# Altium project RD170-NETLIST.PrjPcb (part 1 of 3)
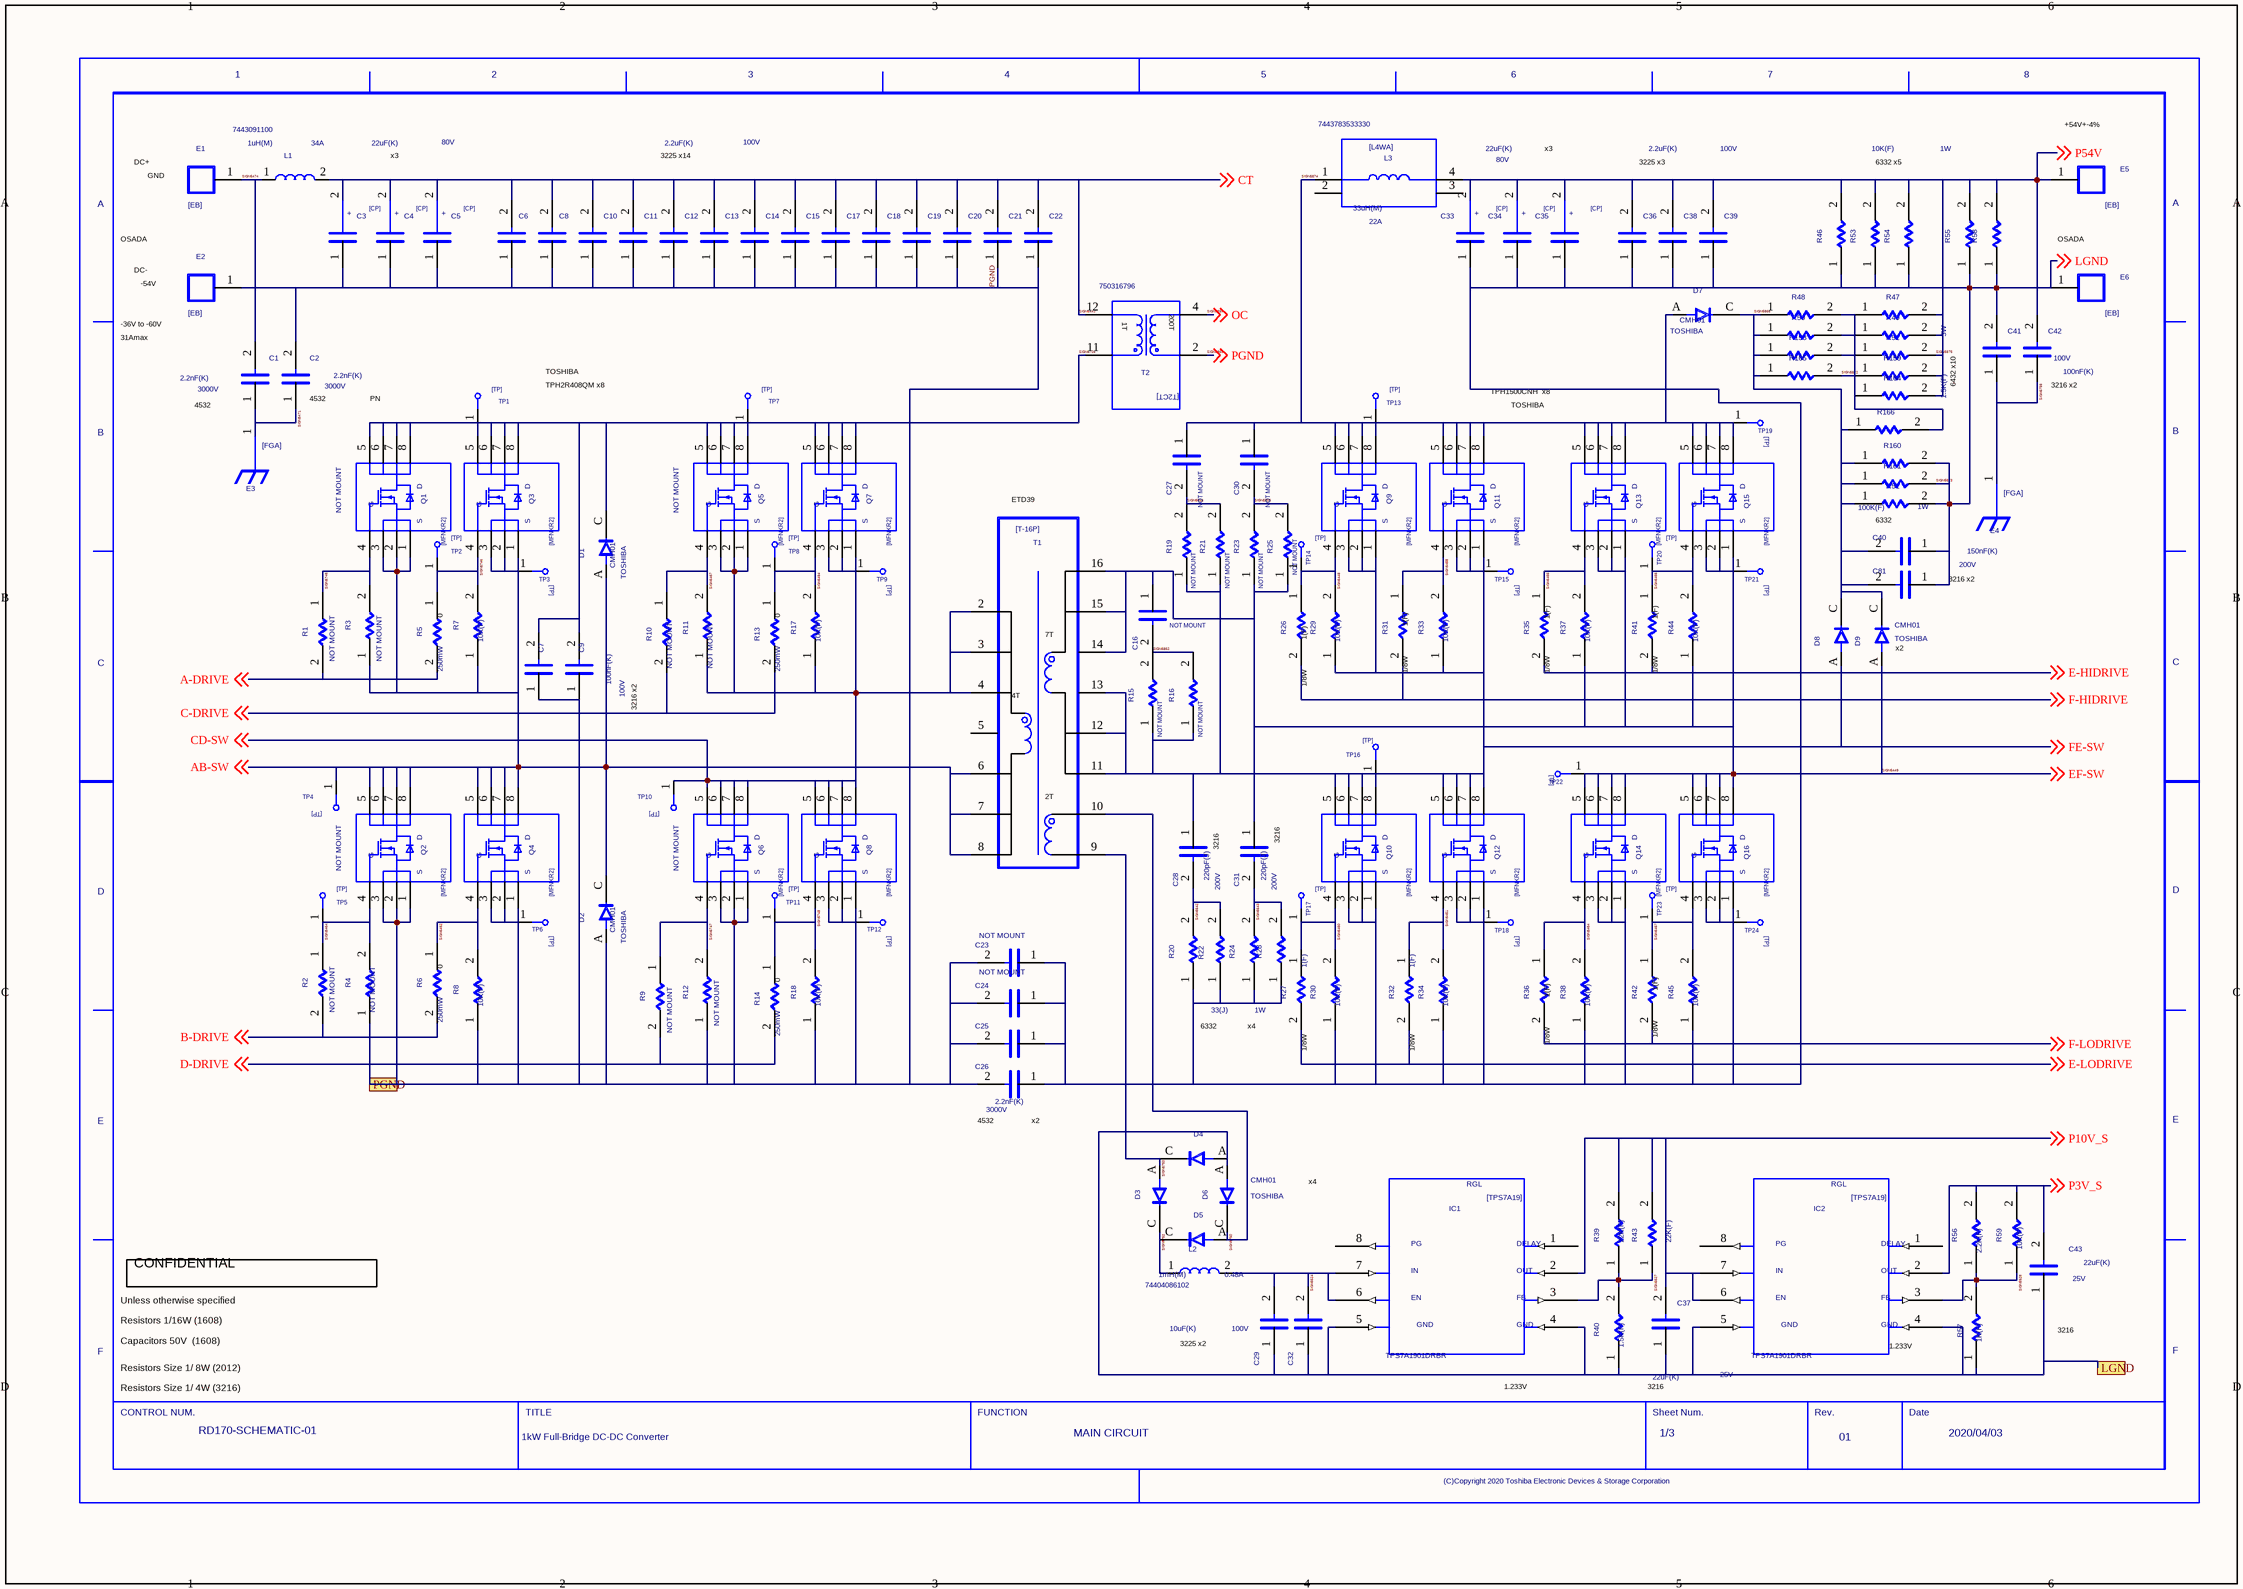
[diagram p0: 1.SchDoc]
3 sheets, 345 parts. Net scope: flat (ports and power ports of the same name join across sheets).
Sheets:
  1.SchDoc
  2.SchDoc
  3.SchDoc

## Sheet 1.SchDoc
size 420 x 297 mm

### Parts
(Parts that share a designator on the sheet are numbered #1, #2 ... from top to bottom, then left to right.)
C1  VAL2: 3000V  VAL1: 2.2nF(K)  (hidden comment: C)
C2  VAL2: 3000V  VAL1: 2.2nF(K)  (hidden comment: C)
C3  CP  (value not drawn)
C4  VAL2: 80V  VAL1: 22uF(K)  (hidden comment: CP)
C5  CP  (value not drawn)
C6  C  (value not drawn)
C7  C  (value not drawn)
C8  C  (value not drawn)
C9  VAL2: 100V  VAL1: 100nF(K)  (hidden comment: C)
C10  C  (value not drawn)
C11  C  (value not drawn)
C12  C  (value not drawn)
C13  VAL2: 100V  VAL1: 2.2uF(K)  (hidden comment: C)
C14  C  (value not drawn)
C15  C  (value not drawn)
C16  NOTMOUNT: NOT MOUNT  (hidden comment: C)
C17  C  (value not drawn)
C18  C  (value not drawn)
C19  C  (value not drawn)
C20  C  (value not drawn)
C21  C  (value not drawn)
C22  C  (value not drawn)
C23  NOTMOUNT: NOT MOUNT  (hidden comment: C)
C24  NOTMOUNT: NOT MOUNT  (hidden comment: C)
C25  C  (value not drawn)
C26  VAL2: 3000V  VAL1: 2.2nF(K)  (hidden comment: C)
C27  NOTMOUNT: NOT MOUNT  (hidden comment: C)
C28  VAL2: 200V  VAL1: 220pF(J)  (hidden comment: C)
C29  VAL2: 100V  VAL1: 10uF(K)  (hidden comment: C)
C30  NOTMOUNT: NOT MOUNT  (hidden comment: C)
C31  VAL2: 200V  VAL1: 220pF(J)  (hidden comment: C)
C32  C  (value not drawn)
C33  VAL2: 80V  VAL1: 22uF(K)  (hidden comment: CP)
C34  CP  (value not drawn)
C35  CP  (value not drawn)
C36  C  (value not drawn)
C37  VAL2: 25V  VAL1: 22uF(K)  (hidden comment: C)
C38  VAL2: 100V  VAL1: 2.2uF(K)  (hidden comment: C)
C39  C  (value not drawn)
C40  VAL2: 200V  VAL1: 150nF(K)  (hidden comment: C)
C41  C  (value not drawn)
C42  VAL2: 100V  VAL1: 100nF(K)  (hidden comment: C)
C43  VAL2: 25V  VAL1: 22uF(K)  (hidden comment: C)
C81  C  (value not drawn)
D1  USERCOMPTEXT3: TOSHIBA  VAL3: CMH01  (hidden comment: D)
D2  USERCOMPTEXT3: TOSHIBA  VAL3: CMH01  (hidden comment: D)
D3  D  (value not drawn)
D4  D  (value not drawn)
D5  D  (value not drawn)
D6  USERCOMPTEXT3: TOSHIBA  VAL3: CMH01  (hidden comment: D)
D7  USERCOMPTEXT3: TOSHIBA  VAL3: CMH01  (hidden comment: D)
D8  D  (value not drawn)
D9  USERCOMPTEXT3: TOSHIBA  VAL3: CMH01  (hidden comment: D)
E1  EB  (value not drawn)
E2  EB  (value not drawn)
E3  FGA  (value not drawn)
E4  FGA  (value not drawn)
E5  EB  (value not drawn)
E6  EB  (value not drawn)
IC1  VAL3: TPS7A1901DRBR  (hidden comment: TPS7A19)
IC2  VAL3: TPS7A1901DRBR  (hidden comment: TPS7A19)
L1  VAL3: 7443091100  VAL2: 34A  VAL1: 1uH(M)  (hidden comment: L)
L2  VAL3: 74404086102  VAL2: 0.48A  VAL1: 1mH(M)  (hidden comment: L)
L3  VAL3: 7443783533330  VAL2: 22A  VAL1: 33uH(M)  (hidden comment: L4WA)
Q1  NOTMOUNT: NOT MOUNT  (hidden comment: MFNKR2)
Q2  NOTMOUNT: NOT MOUNT  (hidden comment: MFNKR2)
Q3  MFNKR2  (value not drawn)
Q4  MFNKR2  (value not drawn)
Q5  NOTMOUNT: NOT MOUNT  (hidden comment: MFNKR2)
Q6  NOTMOUNT: NOT MOUNT  (hidden comment: MFNKR2)
Q7  MFNKR2  (value not drawn)
Q8  MFNKR2  (value not drawn)
Q9  MFNKR2  (value not drawn)
Q10  MFNKR2  (value not drawn)
Q11  MFNKR2  (value not drawn)
Q12  MFNKR2  (value not drawn)
Q13  MFNKR2  (value not drawn)
Q14  MFNKR2  (value not drawn)
Q15  MFNKR2  (value not drawn)
Q16  MFNKR2  (value not drawn)
R1  NOTMOUNT: NOT MOUNT  (hidden comment: R)
R2  NOTMOUNT: NOT MOUNT  (hidden comment: R)
R3  NOTMOUNT: NOT MOUNT  (hidden comment: R)
R4  NOTMOUNT: NOT MOUNT  (hidden comment: R)
R5  VAL2: 250mW  (hidden comment: R)
R6  VAL2: 250mW  (hidden comment: R)
R7  VAL1: 10K(F)  (hidden comment: R)
R8  VAL1: 10K(F)  (hidden comment: R)
R9  NOTMOUNT: NOT MOUNT  (hidden comment: R)
R10  NOTMOUNT: NOT MOUNT  (hidden comment: R)
R11  NOTMOUNT: NOT MOUNT  (hidden comment: R)
R12  NOTMOUNT: NOT MOUNT  (hidden comment: R)
R13  VAL2: 250mW  (hidden comment: R)
R14  VAL2: 250mW  (hidden comment: R)
R15  NOTMOUNT: NOT MOUNT  (hidden comment: R)
R16  NOTMOUNT: NOT MOUNT  (hidden comment: R)
R17  VAL1: 10K(F)  (hidden comment: R)
R18  VAL1: 10K(F)  (hidden comment: R)
R19  NOTMOUNT: NOT MOUNT  (hidden comment: R)
R20  VAL2: 1W  VAL1: 33(J)  (hidden comment: R)
R21  NOTMOUNT: NOT MOUNT  (hidden comment: R)
R22  R  (value not drawn)
R23  NOTMOUNT: NOT MOUNT  (hidden comment: R)
R24  R  (value not drawn)
R25  NOTMOUNT: NOT MOUNT  (hidden comment: R)
R26  R  (value not drawn)
R27  VAL1: 1(F)  (hidden comment: R)
R28  R  (value not drawn)
R29  VAL1: 10K(F)  (hidden comment: R)
R30  VAL1: 10K(F)  (hidden comment: R)
R31  R  (value not drawn)
R32  VAL1: 1(F)  (hidden comment: R)
R33  VAL1: 10K(F)  (hidden comment: R)
R34  VAL1: 10K(F)  (hidden comment: R)
R35  R  (value not drawn)
R36  R  (value not drawn)
R37  VAL1: 10K(F)  (hidden comment: R)
R38  VAL1: 10K(F)  (hidden comment: R)
R39  VAL1: 22K(F)  (hidden comment: R)
R40  VAL1: 1.5K(F)  (hidden comment: R)
R41  R  (value not drawn)
R42  R  (value not drawn)
R43  VAL1: 22K(F)  (hidden comment: R)
R44  VAL1: 10K(F)  (hidden comment: R)
R45  VAL1: 10K(F)  (hidden comment: R)
R46  R  (value not drawn)
R47  R  (value not drawn)
R48  R  (value not drawn)
R49  R  (value not drawn)
R50  R  (value not drawn)
R51  VAL2: 3W  VAL1: 1.5K(F)  (hidden comment: R)
R52  VAL2: 1W  VAL1: 100K(F)  (hidden comment: R)
R53  R  (value not drawn)
R54  VAL2: 1W  VAL1: 10K(F)  (hidden comment: R)
R55  R  (value not drawn)
R56  VAL1: 2.2K(F)  (hidden comment: R)
R57  VAL1: 1K(F)  (hidden comment: R)
R58  R  (value not drawn)
R59  VAL1: 10K(F)  (hidden comment: R)
R158  R  (value not drawn)
R159  R  (value not drawn)
R160  R  (value not drawn)
R161  R  (value not drawn)
R164  R  (value not drawn)
R165  R  (value not drawn)
R166  R  (value not drawn)
T1  T-16P  (value not drawn)
T2  VAL3: 750316796  (hidden comment: T2CT)
TP1  TP  (value not drawn)
TP2  TP  (value not drawn)
TP3  TP  (value not drawn)
TP4  TP  (value not drawn)
TP5  TP  (value not drawn)
TP6  TP  (value not drawn)
TP7  TP  (value not drawn)
TP8  TP  (value not drawn)
TP9  TP  (value not drawn)
TP10  TP  (value not drawn)
TP11  TP  (value not drawn)
TP12  TP  (value not drawn)
TP13  TP  (value not drawn)
TP14  TP  (value not drawn)
TP15  TP  (value not drawn)
TP16  TP  (value not drawn)
TP17  TP  (value not drawn)
TP18  TP  (value not drawn)
TP19  TP  (value not drawn)
TP20  TP  (value not drawn)
TP21  TP  (value not drawn)
TP22  TP  (value not drawn)
TP23  TP  (value not drawn)
TP24  TP  (value not drawn)
U?#1  DATE: 2020/04/03  TITLE: 1kW Full-Bridge DC-DC Converter  REVISION: 01  SHEETNUMBER: 1/3  FUNCTION: MAIN CIRCUIT  DRAWINGNUMBER: RD170-SCHEMATIC-01  (hidden comment: WAKU_DEF100)

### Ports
LGND, PGND

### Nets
A-DRIVE: R1.2 R5.2 ; off-sheet A-DRIVE
AB-SW: D1.A D2.C Q1.1 Q1.2 Q1.3 Q2.5 Q2.6 Q2.7 Q2.8 Q3.1 Q3.2 Q3.3 Q4.5 Q4.6 Q4.7 Q4.8 R3.1 R7.1 T1.6 T1.7 T1.8 TP3.1 TP4.1 ; off-sheet AB-SW
B-DRIVE: R2.2 R6.2 ; off-sheet B-DRIVE
C-DRIVE: R10.2 R13.2 ; off-sheet C-DRIVE
CD-SW: Q5.1 Q5.2 Q5.3 Q6.5 Q6.6 Q6.7 Q6.8 Q7.1 Q7.2 Q7.3 Q8.5 Q8.6 Q8.7 Q8.8 R11.1 R17.1 T1.2 T1.3 T1.4 TP9.1 TP10.1 ; off-sheet CD-SW
D-DRIVE: R9.2 R14.2 ; off-sheet D-DRIVE
E-HIDRIVE: R35.2 R41.2 ; off-sheet E-HIDRIVE
E-LODRIVE: R27.2 R32.2 ; off-sheet E-LODRIVE
F-HIDRIVE: R26.2 R31.2 ; off-sheet F-HIDRIVE
F-LODRIVE: R36.2 R42.2 ; off-sheet F-LODRIVE
FE-SW: C28.1 D8.A Q9.1 Q9.2 Q9.3 Q10.5 Q10.6 Q10.7 Q10.8 Q11.1 Q11.2 Q11.3 Q12.5 Q12.6 Q12.7 Q12.8 R15.1 R16.1 R19.1 R21.1 R29.1 R33.1 T1.11 T1.12 T1.13 TP15.1 TP16.1 ; off-sheet FE-SW
P3V_S: C43.2 IC2.2 R56.2 R59.2 ; off-sheet P3V_S
P10V_S: C37.2 IC1.2 IC2.6 IC2.7 R39.2 R43.2 ; off-sheet P10V_S
PGND: C2.2 C3.1 C4.1 C5.1 C6.1 C7.1 C8.1 C9.1 C10.1 C11.1 C12.1 C13.1 C14.1 C15.1 C17.1 C18.1 C19.1 C20.1 C21.1 C22.1 C23.2 C24.2 C25.2 C26.2 D2.A E2.1 Q2.1 Q2.2 Q2.3 Q4.1 Q4.2 Q4.3 Q6.1 Q6.2 Q6.3 Q8.1 Q8.2 Q8.3 R4.1 R8.1 R12.1 R18.1 T2.2 TP6.1 TP12.1 ; off-sheet PGND, port PGND  [also labelled SIGN5865]
SIGN5443: C3.2 C4.2 C5.2 C6.2 C8.2 C10.2 C11.2 C12.2 C13.2 C14.2 C15.2 C17.2 C18.2 C19.2 C20.2 C21.2 C22.2 L1.2 T2.12 ; off-sheet CT  [also labelled CT]
SIGN5448: Q9.4 R26.1 R29.2 TP14.1
SIGN5449: C16.1 C31.1 D9.A Q13.1 Q13.2 Q13.3 Q14.5 Q14.6 Q14.7 Q14.8 Q15.1 Q15.2 Q15.3 Q16.5 Q16.6 Q16.7 Q16.8 R23.1 R25.1 R37.1 R44.1 T1.14 T1.15 T1.16 TP21.1 TP22.1 ; off-sheet EF-SW  [also labelled EF-SW]
SIGN5450: Q10.4 R27.1 R30.2 TP17.1
SIGN5451: Q12.4 R32.1 R34.2
SIGN5454: Q14.4 R36.1 R38.2
SIGN5455: Q13.4 R35.1 R37.2
SIGN5456: Q15.4 R41.1 R44.2 TP20.1
SIGN5457: Q16.4 R42.1 R45.2 TP23.1
SIGN5458: Q11.4 R31.1 R33.2
SIGN5464: Q2.4 R2.1 R4.2 TP5.1
SIGN5467: Q5.4 R10.1 R11.2
SIGN5471: C1.1 C2.1 E3.1
SIGN5474: C1.2 E1.1 L1.1
SIGN5482: Q4.4 R6.1 R8.2
SIGN5484: Q7.4 R13.1 R17.2 TP8.1
SIGN5524: C29.2 C32.2 IC1.6 IC1.7 L2.2
SIGN5527: IC1.3 R39.1 R40.2 R43.1
SIGN5528: IC2.3 R56.1 R57.2 R59.1
SIGN5542: C28.2 R20.2 R22.2
SIGN5543: C31.2 R24.2 R28.2
SIGN5726: C7.2 C9.2 D1.C Q1.5 Q1.6 Q1.7 Q1.8 Q3.5 Q3.6 Q3.7 Q3.8 Q5.5 Q5.6 Q5.7 Q5.8 Q7.5 Q7.6 Q7.7 Q7.8 T2.11 TP1.1 TP7.1
SIGN5745: Q1.4 R1.1 R3.2
SIGN5746: Q3.4 R5.1 R7.2 TP2.1
SIGN5747: Q6.4 R9.1 R12.2
SIGN5748: Q8.4 R14.1 R18.2 TP11.1
SIGN5750: D5.A D6.C T1.10
SIGN5752: D3.C D5.C L2.1
SIGN5753: D3.A D4.C T1.9
SIGN5756: C41.1 C42.1 E4.1
SIGN5855: C30.2 R23.2 R25.2
SIGN5856: C27.2 R19.2 R21.2
SIGN5862: C16.2 R15.2 R16.2
SIGN5864: T2.4 ; off-sheet OC  [also labelled OC]
SIGN5866: C40.2 C81.2 D7.C D8.C D9.C R48.1 R50.1 R52.1 R158.1 R160.1 R161.1 R165.1 R166.1
SIGN5872: R47.1 R48.2 R49.1 R50.2 R51.1 R158.2 R159.1 R164.1 R165.2 R166.2
SIGN5873: C23.1 C24.1 C25.1 C26.1 C29.1 C32.1 C33.1 C34.1 C35.1 C36.1 C37.1 C38.1 C39.1 C40.1 C41.2 C43.1 C81.1 D4.A D6.A E6.1 IC1.4 IC1.5 IC2.4 IC2.5 Q10.1 Q10.2 Q10.3 Q12.1 Q12.2 Q12.3 Q14.1 Q14.2 Q14.3 Q16.1 Q16.2 Q16.3 R20.1 R22.1 R24.1 R28.1 R30.1 R34.1 R38.1 R40.1 R45.1 R46.1 R52.2 R53.1 R54.1 R55.1 R57.1 R58.1 R160.2 R161.2 TP18.1 TP24.1 ; off-sheet LGND, port LGND  [also labelled LGND]
SIGN5874: C27.1 C30.1 D7.A L3.1 Q9.5 Q9.6 Q9.7 Q9.8 Q11.5 Q11.6 Q11.7 Q11.8 Q13.5 Q13.6 Q13.7 Q13.8 Q15.5 Q15.6 Q15.7 Q15.8 TP13.1 TP19.1
SIGN5875: C33.2 C34.2 C35.2 C36.2 C38.2 C39.2 C42.2 E5.1 L3.4 R46.2 R47.2 R49.2 R51.2 R53.2 R54.2 R55.2 R58.2 R159.2 R164.2 ; off-sheet P54V  [also labelled P54V]

Not connected (* = marked no-connect by the designer): IC1 1 8; IC2 1 8; L3 2 3; T1 5

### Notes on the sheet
- (near E5) +54V+-4%
  18.5A
- DC+
- GND
- x3
- 3225 x14
- 3225 x3
- 6332 x5
- OSADA
  OP-486 (50A)
- OSADA
  OP-486
  (50A)
- -36V to -60V
- DC-
- -54V
- (near T2) 1T
- (near T2) 200T
- 31Amax
- TPH2R408QM x8
- TOSHIBA
- TPH1500CNH  x8
- 6432 x10
- (near C42) 3216 x2
- 4532
- (near C2) 4532
- PN
- ETD39
- (near R52) 6332
- 3216 x2
- (near R5) 0
- (near R13) 0
- (near T1) 7T
- (near R26) 1(F)
- (near R31) 1(F)
- (near R35) 1(F)
- (near R41) 1(F)
- (near D9) x2
- (near T1) 4T
- 1/8W
- (near R31) 1/8W
- (near R35) 1/8W
- (near R41) 1/8W
- (near T1) 2T
- 3216
- (near C31) 3216
- (near R6) 0
- (near R14) 0
- (near R36) 1(F)
- (near R42) 1(F)
- 6332
- x4
- (near R42) 1/8W
- (near C26) 4532
- (near C26) x2
- CONFIDENTIAL
- Unless otherwise specified
- Capacitors 50V  (1608)
- Resistors 1/16W (1608)
- 1.233V
  +-0.2%
- Resistors Size 1/ 8W (2012)
- Resistors Size 1/ 4W (3216)
- 3225 x2

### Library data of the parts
C1 C2 C26 = C: USEINPARTSLIST: YES; PARTNAME: 885342211010; OriginalSymbolOrigin: (2540,7620); QUADMODEL: CON_2.2n; VAL3: 8.85E+11; MAXGCOUNT: 1; COMPONENTNAME: pinass:C_func:C; OUMEMAKER: WURTH
C3 C5 C34 C35 = CP: USEINPARTSLIST: YES; PARTNAME: 875076161003; OriginalSymbolOrigin: (2540,12700); QUADMODEL: CON_22u; VAL3: 8.75E+11; VAL2: 80V; VAL1: 22uF(K); COMPONENTNAME: pinass:CP_func:CP; MAXGCOUNT: 1; OUMEMAKER: WURTH
C4 C33 = CP: USEINPARTSLIST: YES; PARTNAME: 875076161003; OriginalSymbolOrigin: (2540,12700); QUADMODEL: CON_22u; VAL3: 8.75E+11; COMPONENTNAME: pinass:CP_func:CP; MAXGCOUNT: 1; OUMEMAKER: WURTH
C6 C8 C10-C12 C14 C15 C17-C22 C36 C39 = C: SQ_PART_MODEL: CON_2.2u; FNPARTSNAMEG: CHIP M-PEN FILM CAPACITOR; USEINPARTSLIST: YES; PARTNAME: G36030013017; OriginalSymbolOrigin: (2540,7620); PCODE: P03102001111; RATEDVOLTAGE: 16; COMPONENTNAME: G36030013017_package; MAXGCOUNT: 1; MFSOLDERINGPROP: .; OUMEMAKER: NAT 松下電器産業; MFPACKAGEMETHOP: S; MFFORMINGDIVP: KC; OUMECLASSIFICATION: フィルャRンデンサ; SIZECODESMD: 3225; NOMINALCAPACITA: 100n; MFMOUNTSYMBOLP: 80; OUMEMAKERKATAMEI: ECWU1C104JB5; VAL3: 8.85E+11; VAL2: 100V; VAL1: 2.2uF(K); CAPACITANCETOLE: J; CDMASTERCADCELG: C8101B; FNCLASSCODEG: P03-05
C7 C41 = C: SQ_PART_MODEL: CON_100n; FNPARTSNAMEG: CHIP CERAMIC CAPACITOR (3216); USEINPARTSLIST: YES; PARTNAME: GDM030000693; OriginalSymbolOrigin: (2540,7620); MFSOLDERINGPROP: .; TEMPCHARACTERI2: B; MFFORMINGDIVP: KC; OUMECLASSIFICATION: セラミックコンデンサ; SIZECODESMD: 3216; MFMOUNTSYMBOLP: 90; CDMASTERCADCELG: DC901A; PCODE: P03042030127; FNCLASSCODEG: P03-03; MAXGCOUNT: 1; RATEDVOLTAGE: 50; COMPONENTNAME: GDM030000693_package; OUMEMAKER: KYC 京セラ; MFPACKAGEMETHOP: S; NOMINALCAPACITA: 100n; OUMEMAKERKATAMEI: CM316W5R104K50AT; VAL2: 100V; VAL1: 100nF(K); CAPACITANCETOLE: K
C9 C42 = C: SQ_PART_MODEL: CON_100n; FNPARTSNAMEG: CHIP CERAMIC CAPACITOR (3216); USEINPARTSLIST: YES; PARTNAME: GDM030000693; OriginalSymbolOrigin: (2540,7620); MFSOLDERINGPROP: .; TEMPCHARACTERI2: B; MFFORMINGDIVP: KC; OUMECLASSIFICATION: セラミックコンデンサ; SIZECODESMD: 3216; MFMOUNTSYMBOLP: 90; CDMASTERCADCELG: DC901A; PCODE: P03042030127; FNCLASSCODEG: P03-03; MAXGCOUNT: 1; RATEDVOLTAGE: 50; COMPONENTNAME: GDM030000693_package; OUMEMAKER: KYC 京セラ; MFPACKAGEMETHOP: S; NOMINALCAPACITA: 100n; OUMEMAKERKATAMEI: CM316W5R104K50AT; CAPACITANCETOLE: K
C13 C38 = C: SQ_PART_MODEL: CON_2.2u; FNPARTSNAMEG: CHIP M-PEN FILM CAPACITOR; USEINPARTSLIST: YES; PARTNAME: G36030013017; OriginalSymbolOrigin: (2540,7620); PCODE: P03102001111; RATEDVOLTAGE: 16; COMPONENTNAME: G36030013017_package; MAXGCOUNT: 1; MFSOLDERINGPROP: .; OUMEMAKER: NAT 松下電器産業; MFPACKAGEMETHOP: S; MFFORMINGDIVP: KC; OUMECLASSIFICATION: フィルャRンデンサ; SIZECODESMD: 3225; NOMINALCAPACITA: 100n; MFMOUNTSYMBOLP: 80; OUMEMAKERKATAMEI: ECWU1C104JB5; VAL3: 8.85E+11; CAPACITANCETOLE: J; CDMASTERCADCELG: C8101B; FNCLASSCODEG: P03-05
C16 C27 C30 = C: FNPARTSNAMEG: CHIP CERAMIC CAPACITOR (3216); USEINPARTSLIST: YES; PARTNAME: GDM030000693; OriginalSymbolOrigin: (2540,7620); PCODE: P03042030127; RATEDVOLTAGE: 50; COMPONENTNAME: GDM030000693_package; MAXGCOUNT: 1; MFSOLDERINGPROP: .; TEMPCHARACTERI2: B; OUMEMAKER: KYC 京セラ; MFPACKAGEMETHOP: S; MFFORMINGDIVP: KC; OUMECLASSIFICATION: セラミックコンデンサ; SIZECODESMD: 3216; NOMINALCAPACITA: 100n; MFMOUNTSYMBOLP: 90; OUMEMAKERKATAMEI: CM316W5R104K50AT; CAPACITANCETOLE: K; CDMASTERCADCELG: DC901A; FNCLASSCODEG: P03-03
C23 C24 = C: USEINPARTSLIST: YES; PARTNAME: 885342211010; OriginalSymbolOrigin: (2540,7620); MAXGCOUNT: 1; COMPONENTNAME: pinass:C_func:C; OUMEMAKER: WURTH
C25 = C: USEINPARTSLIST: YES; PARTNAME: 885342211010; OriginalSymbolOrigin: (2540,7620); QUADMODEL: CON_2.2n; VAL3: 8.85E+11; VAL2: 3000V; VAL1: 2.2nF(K); MAXGCOUNT: 1; COMPONENTNAME: pinass:C_func:C; OUMEMAKER: WURTH
C28 C31 = C: SQ_PART_MODEL: CON_220p; FNPARTSNAMEG: CHIP CERAMIC CAPACITOR (3216); USEINPARTSLIST: YES; PARTNAME: GDM030000693; OriginalSymbolOrigin: (2540,7620); PCODE: P03042030127; RATEDVOLTAGE: 50; COMPONENTNAME: GDM030000693_package; MAXGCOUNT: 1; MFSOLDERINGPROP: .; TEMPCHARACTERI2: B; OUMEMAKER: KYC 京セラ; MFPACKAGEMETHOP: S; MFFORMINGDIVP: KC; OUMECLASSIFICATION: セラミックコンデンサ; SIZECODESMD: 3216; NOMINALCAPACITA: 100n; MFMOUNTSYMBOLP: 90; OUMEMAKERKATAMEI: CM316W5R104K50AT; CAPACITANCETOLE: K; CDMASTERCADCELG: DC901A; FNCLASSCODEG: P03-03
C29 = C: SQ_PART_MODEL: CON_10u; FNPARTSNAMEG: CHIP CERAMIC CAPACITOR (3216); USEINPARTSLIST: YES; PARTNAME: G36030013017; OriginalSymbolOrigin: (2540,7620); PCODE: P03042030127; MAXGCOUNT: 1; RATEDVOLTAGE: 50; COMPONENTNAME: GDM030000693_package; MFSOLDERINGPROP: .; TEMPCHARACTERI2: B; OUMEMAKER: KYC 京セラ; MFPACKAGEMETHOP: S; MFFORMINGDIVP: KC; OUMECLASSIFICATION: セラミックコンデンサ; SIZECODESMD: 3216; FUNCTION: GDM030000693; MFMOUNTSYMBOLP: 90; OUMEMAKERKATAMEI: CM316W5R104K50AT; VAL3: GRM32EC72A106KE05#; CAPACITANCETOLE: K; CDMASTERCADCELG: DC901A; FNCLASSCODEG: P03-03; NOMINALCAPACITA: 100n
C32 = C: SQ_PART_MODEL: CON_10u; FNPARTSNAMEG: CHIP CERAMIC CAPACITOR (3216); USEINPARTSLIST: YES; PARTNAME: G36030013017; OriginalSymbolOrigin: (2540,7620); PCODE: P03042030127; MAXGCOUNT: 1; RATEDVOLTAGE: 50; COMPONENTNAME: GDM030000693_package; MFSOLDERINGPROP: .; TEMPCHARACTERI2: B; OUMEMAKER: KYC 京セラ; MFPACKAGEMETHOP: S; MFFORMINGDIVP: KC; OUMECLASSIFICATION: セラミックコンデンサ; SIZECODESMD: 3216; FUNCTION: GDM030000693; MFMOUNTSYMBOLP: 90; OUMEMAKERKATAMEI: CM316W5R104K50AT; VAL3: GRM32EC72A106KE05#; VAL2: 100V; VAL1: 10uF(K); CAPACITANCETOLE: K; CDMASTERCADCELG: DC901A; FNCLASSCODEG: P03-03; NOMINALCAPACITA: 100n
C37 = C: SQ_PART_MODEL: CON_22u; FNPARTSNAMEG: CHIP CERAMIC CAPACITOR (2012); USEINPARTSLIST: YES; PARTNAME: GDM030000693; OriginalSymbolOrigin: (2540,7620); PCODE: P03261001113; MAXGCOUNT: 1; RATEDVOLTAGE: 25; COMPONENTNAME: G36030029759_package; MFSOLDERINGPROP: .; TEMPCHARACTERI2: B; OUMEMAKER: KYC 京セラ; MFPACKAGEMETHOP: S; MFFORMINGDIVP: KC; OUMECLASSIFICATION: セラミックコンデンサ; SIZECODESMD: 2012; FUNCTION: G36030029759; MFMOUNTSYMBOLP: 90; OUMEMAKERKATAMEI: CM21B474K25AT; VAL3: GRM31CC81E226ME11#; CAPACITANCETOLE: K; CDMASTERCADCELG: DC910A; FNCLASSCODEG: P03-03; NOMINALCAPACITA: 470n
C40 = C: SQ_PART_MODEL: CON_150n; FNPARTSNAMEG: CHIP CERAMIC CAPACITOR (3216); USEINPARTSLIST: YES; PARTNAME: GDM030000693; OriginalSymbolOrigin: (2540,7620); TEMPCHARACTERI2: B; MFMOUNTSYMBOLP: 90; PCODE: P03042030127; RATEDVOLTAGE: 50; COMPONENTNAME: GDM030000693_package; MAXGCOUNT: 1; MFSOLDERINGPROP: .; OUMEMAKER: KYC 京セラ; MFPACKAGEMETHOP: S; MFFORMINGDIVP: KC; OUMECLASSIFICATION: セラミックコンデンサ; SIZECODESMD: 3216; NOMINALCAPACITA: 100n; OUMEMAKERKATAMEI: CM316W5R104K50AT; CAPACITANCETOLE: K; CDMASTERCADCELG: DC901A; FNCLASSCODEG: P03-03
C43 = C: SQ_PART_MODEL: CON_22u; FNPARTSNAMEG: CHIP CERAMIC CAPACITOR (2012); USEINPARTSLIST: YES; PARTNAME: GDM030000693; OriginalSymbolOrigin: (2540,7620); PCODE: P03261001113; RATEDVOLTAGE: 25; COMPONENTNAME: G36030029759_package; MAXGCOUNT: 1; MFSOLDERINGPROP: .; TEMPCHARACTERI2: B; OUMEMAKER: KYC 京セラ; MFPACKAGEMETHOP: S; MFFORMINGDIVP: KC; OUMECLASSIFICATION: セラミックコンデンサ; SIZECODESMD: 2012; FUNCTION: G36030029759; NOMINALCAPACITA: 470n; MFMOUNTSYMBOLP: 90; OUMEMAKERKATAMEI: CM21B474K25AT; VAL3: GRM31CC81E226ME11#; CAPACITANCETOLE: K; CDMASTERCADCELG: DC910A; FNCLASSCODEG: P03-03
C81 = C: SQ_PART_MODEL: CON_150n; FNPARTSNAMEG: CHIP CERAMIC CAPACITOR (3216); USEINPARTSLIST: YES; PARTNAME: GDM030000693; OriginalSymbolOrigin: (2540,7620); TEMPCHARACTERI2: B; MFMOUNTSYMBOLP: 90; PCODE: P03042030127; RATEDVOLTAGE: 50; COMPONENTNAME: GDM030000693_package; MAXGCOUNT: 1; MFSOLDERINGPROP: .; OUMEMAKER: KYC 京セラ; MFPACKAGEMETHOP: S; MFFORMINGDIVP: KC; OUMECLASSIFICATION: セラミックコンデンサ; SIZECODESMD: 3216; NOMINALCAPACITA: 100n; OUMEMAKERKATAMEI: CM316W5R104K50AT; VAL2: 200V; VAL1: 150nF(K); CAPACITANCETOLE: K; CDMASTERCADCELG: DC901A; FNCLASSCODEG: P03-03
D1 D2 D6 D7 D9 = D: USEINPARTSLIST: YES; PARTNAME: 5P9L1110P002; SAVEAREA0: -565,-171,12979,8058; SAVECOUNT: 1; OriginalSymbolOrigin: (2540,5080); COMPONENTNAME: D_D; OUMEMAKER: 東芝; OUMEMAKERKATAMEI: CMF02(TE12R,Q); VAL1: CMH01(TE12L,Q)
D3-D5 = D: USEINPARTSLIST: YES; PARTNAME: 5P9L1110P002; SAVEAREA0: -565,-171,12979,8058; SAVECOUNT: 1; OriginalSymbolOrigin: (2540,5080); COMPONENTNAME: D_D; OUMEMAKER: 東芝; OUMEMAKERKATAMEI: CMF02(TE12R,Q); VAL3: CMH01(TE12L,Q)
D8 = D: USEINPARTSLIST: YES; PARTNAME: 5P9L1110P002; SAVEAREA0: -565,-171,12979,8058; SAVECOUNT: 1; OriginalSymbolOrigin: (2540,5080); USERCOMPTEXT3: TOSHIBA; COMPONENTNAME: D_D; OUMEMAKER: 東芝; OUMEMAKERKATAMEI: CMF02(TE12R,Q); VAL3: CMH01; VAL1: CMH01(TE12L,Q)
E1 E2 E5 E6 = EB: USEINPARTSLIST: YES; OriginalSymbolOrigin: (2540,12700); VAL3: OP-486; COMPONENTNAME: pinass:EB_func:EB; MAXGCOUNT: 1; OUMEMAKER: オサダ
E3 E4 = FGA: PARTNAME: ZS_SHFG38; USEINPARTSLIST: YES; OUMEPARTTYPE: PJ; OriginalSymbolOrigin: (0,10160); MAXGCOUNT: 1; COMPONENTNAME: ZS_SHFG38_package; QUADMODEL: dummymodel; OUMECELLMEI: SHFG38; PA_PHASE: SCH; PA_LOCK: LOCKED
IC1 IC2 = TPS7A19: USEINPARTSLIST: YES; SAVEAREA0: 0,-963,45720,33942; SAVECOUNT: 69; TIME: 14:04:55; UPDATEUSER: q91866sr; UPDATETIME: 17:23:08; OriginalSymbolOrigin: (7620,33020); MAXGCOUNT: 1; COMPONENTNAME: pinass:TPS7A19_func:TPS7A19; OUMEMAKER: TI
L1 = L: USEINPARTSLIST: YES; OriginalSymbolOrigin: (2540,5080); COMPONENTNAME: pinass:L_func:L; MAXGCOUNT: 1; OUMEMAKER: WURTH
L2 = L: USEINPARTSLIST: YES; OriginalSymbolOrigin: (2540,5080); MAXGCOUNT: 1; COMPONENTNAME: pinass:L_func:L; OUMEMAKER: WURTH
L3 = L4WA: USEINPARTSLIST: YES; SAVECOUNT: 10; SAVEAREA0: -2088,-30,30063,17749; TIME: 11:26:51; UPDATEUSER: q91866sr; UPDATETIME: 09:26:58; OriginalSymbolOrigin: (5080,15240); MAXGCOUNT: 1; COMPONENTNAME: L4WA.L4WA; OUMEMAKER: WURTH
Q1 Q2 Q5 Q6 = MFNKR2: PARTNAME: TPCA8055-H; SAVEAREA0: -9199,-39,32138,22820; TIME: 18:57:44; UPDATEUSER: q91866sr; UPDATETIME: 12:36:02; SAVECOUNT: 10; OriginalSymbolOrigin: (5080,20320)
Q3 Q4 Q7 Q8 = MFNKR2: PARTNAME: TPCA8055-H; SAVEAREA0: -9199,-39,32138,22820; TIME: 18:57:44; UPDATEUSER: q91866sr; UPDATETIME: 12:36:02; SAVECOUNT: 10; OriginalSymbolOrigin: (5080,20320); VAL3: TPH2R408QM
Q9-Q16 = MFNKR2: PARTNAME: TPCA8055-H; SAVEAREA0: -9199,-39,32138,22820; TIME: 18:57:44; UPDATEUSER: q91866sr; UPDATETIME: 12:36:02; SAVECOUNT: 10; OriginalSymbolOrigin: (5080,20320); VAL3: TPH1500CNH
R1 R2 R9 R10 = R: FNPARTSNAMEG: CHIP RESISTOR (3216); USEINPARTSLIST: YES; PARTNAME: G36010101093; OriginalSymbolOrigin: (5080,5080); MAXGCOUNT: 1; COMPONENTNAME: G36010101093_package; MFSOLDERINGPROP: .; OUMEMAKER: NAE 松下電子部品; MFPACKAGEMETHOP: S; MFFORMINGDIVP: KC; MOUNTINGFORMSMD: SMD; OUMECLASSIFICATION: 表面実装用固定抵抗器; RESISTANCETOLER: F; MFMOUNTSYMBOLP: 90; POWERRATING: 250m; OUMEMAKERKATAMEI: ERJ8RQF4R7V; NUMBEROFELEMENT: 0; CDMASTERCADCELG: DR901A; PCODE: P01127006111; FNCLASSCODEG: P01-08; FNLEADFREETHET1GT2GMCTH1: 3_1_N; NOMINALRESISTAN: 4.7; OUMEPOWER: 1/10; OUMERESISTANCE: 8.2K; OUMECHIPSIZE: 2012; OUMECELLMEI: DR910A; PA_PHASE: SCH; PA_LOCK: LOCKED; OUMERANKU: L
R3 R4 R11 R12 = R: FNPARTSNAMEG: CHIP RESISTOR (1608); USEINPARTSLIST: YES; PARTNAME: G36010027034; OriginalSymbolOrigin: (5080,5080); MFSOLDERINGPROP: .; MFPACKAGEMETHOP: S; MFFORMINGDIVP: KC; MOUNTINGFORMSMD: SMD; FNLEADFREETHET1GT2GMCTH1: 3_1_N; OUMECLASSIFICATION: 表面実装用固定抵抗器; RESISTANCETOLER: F; MFMOUNTSYMBOLP: 80; POWERRATING: 63m; NOMINALRESISTAN: 10K; NUMBEROFELEMENT: 0; CDMASTERCADCELG: DR802R; PCODE: P01042049A26; FNCLASSCODEG: P01-08; MAXGCOUNT: 1; OUMEPOWER: 1/10; COMPONENTNAME: G36010027034_package; OUMEMAKER: SAM 三星電機; OUMERESISTANCE: 8.2K; OUMECHIPSIZE: 2012; OUMECELLMEI: DR910A; OUMEMAKERKATAMEI: RC1608F103CS; PA_PHASE: SCH; PA_LOCK: LOCKED; OUMERANKU: L
R5 R6 R13 R14 = R: SQ_PART_MODEL: RES_0; FNPARTSNAMEG: CHIP RESISTOR (3216); USEINPARTSLIST: YES; PARTNAME: G36010101093; OriginalSymbolOrigin: (5080,5080); MAXGCOUNT: 1; COMPONENTNAME: G36010101093_package; MFSOLDERINGPROP: .; OUMEMAKER: NAE 松下電子部品; MFPACKAGEMETHOP: S; MFFORMINGDIVP: KC; MOUNTINGFORMSMD: SMD; OUMECLASSIFICATION: 表面実装用固定抵抗器; RESISTANCETOLER: F; MFMOUNTSYMBOLP: 90; POWERRATING: 250m; OUMEMAKERKATAMEI: ERJ8RQF4R7V; NUMBEROFELEMENT: 0; VAL1: 0(X); CDMASTERCADCELG: DR901A; PCODE: P01127006111; FNCLASSCODEG: P01-08; FNLEADFREETHET1GT2GMCTH1: 3_1_N; NOMINALRESISTAN: 4.7; OUMEPOWER: 1/10; OUMERESISTANCE: 8.2K; OUMECHIPSIZE: 2012; OUMECELLMEI: DR910A; PA_PHASE: SCH; PA_LOCK: LOCKED; OUMERANKU: L
R7 R8 R17 R18 R29 R30 R33 R34 R37 R38 R44 R45 = R: SQ_PART_MODEL: RES_10K; FNPARTSNAMEG: CHIP RESISTOR (1608); USEINPARTSLIST: YES; PARTNAME: G36010027034; OriginalSymbolOrigin: (5080,5080); MFSOLDERINGPROP: .; MFPACKAGEMETHOP: S; MFFORMINGDIVP: KC; MOUNTINGFORMSMD: SMD; FNLEADFREETHET1GT2GMCTH1: 3_1_N; OUMECLASSIFICATION: 表面実装用固定抵抗器; RESISTANCETOLER: F; ASIMVALUE: 10K; MFMOUNTSYMBOLP: 80; POWERRATING: 63m; NUMBEROFELEMENT: 0; CDMASTERCADCELG: DR802R; PCODE: P01042049A26; FNCLASSCODEG: P01-08; MAXGCOUNT: 1; OUMEPOWER: 1/10; COMPONENTNAME: G36010027034_package; OUMEMAKER: SAM 三星電機; OUMERESISTANCE: 8.2K; OUMECHIPSIZE: 2012; OUMECELLMEI: DR910A; OUMEMAKERKATAMEI: RC1608F103CS; VAL2: 63mW; PA_PHASE: SCH; PA_LOCK: LOCKED; OUMERANKU: L
R15 R16 R19 R21 R23 R25 = R: FNPARTSNAMEG: CHIP RESISTOR (6432); USEINPARTSLIST: YES; PARTNAME: G36010105121; OriginalSymbolOrigin: (5080,5080); MFSOLDERINGPROP: .; MFPACKAGEMETHOP: S; MFFORMINGDIVP: KC; MOUNTINGFORMSMD: SMD; FNLEADFREETHET1GT2GMCTH1: 3_1_N; OUMECLASSIFICATION: 表面実装用固定抵抗器; RESISTANCETOLER: J; MFMOUNTSYMBOLP: 80; POWERRATING: 1; NOMINALRESISTAN: 33; NUMBEROFELEMENT: 0; CDMASTERCADCELG: R8100A; PCODE: P01079017210; FNCLASSCODEG: P01-08; OUMEPOWER: 1/10; COMPONENTNAME: G36010105121_package; OUMEMAKER: KOA ＫＯＡ; OUMERESISTANCE: 8.2K; OUMECHIPSIZE: 2012; OUMECELLMEI: DR910A; OUMEMAKERKATAMEI: RK73K3ATE330J; PA_PHASE: SCH; PA_LOCK: LOCKED; OUMERANKU: L
R20 = R: SQ_PART_MODEL: RES_33; FNPARTSNAMEG: CHIP RESISTOR (6432); USEINPARTSLIST: YES; PARTNAME: G36010105121; OriginalSymbolOrigin: (5080,5080); MFSOLDERINGPROP: .; MFPACKAGEMETHOP: S; MFFORMINGDIVP: KC; MOUNTINGFORMSMD: SMD; FNLEADFREETHET1GT2GMCTH1: 3_1_N; OUMECLASSIFICATION: 表面実装用固定抵抗器; RESISTANCETOLER: J; MFMOUNTSYMBOLP: 80; POWERRATING: 1; NOMINALRESISTAN: 33; NUMBEROFELEMENT: 0; CDMASTERCADCELG: R8100A; PCODE: P01079017210; FNCLASSCODEG: P01-08; OUMEPOWER: 1/10; COMPONENTNAME: G36010105121_package; OUMEMAKER: KOA ＫＯＡ; OUMERESISTANCE: 8.2K; OUMECHIPSIZE: 2012; OUMECELLMEI: DR910A; OUMEMAKERKATAMEI: RK73K3ATE330J; PA_PHASE: SCH; PA_LOCK: LOCKED; OUMERANKU: L
R22 R24 R28 = R: SQ_PART_MODEL: RES_33; FNPARTSNAMEG: CHIP RESISTOR (6432); USEINPARTSLIST: YES; PARTNAME: G36010105121; OriginalSymbolOrigin: (5080,5080); MFSOLDERINGPROP: .; MFPACKAGEMETHOP: S; MFFORMINGDIVP: KC; MOUNTINGFORMSMD: SMD; FNLEADFREETHET1GT2GMCTH1: 3_1_N; OUMECLASSIFICATION: 表面実装用固定抵抗器; RESISTANCETOLER: J; MFMOUNTSYMBOLP: 80; POWERRATING: 1; NOMINALRESISTAN: 33; NUMBEROFELEMENT: 0; CDMASTERCADCELG: R8100A; PCODE: P01079017210; FNCLASSCODEG: P01-08; OUMEPOWER: 1/10; COMPONENTNAME: G36010105121_package; OUMEMAKER: KOA ＫＯＡ; OUMERESISTANCE: 8.2K; OUMECHIPSIZE: 2012; OUMECELLMEI: DR910A; OUMEMAKERKATAMEI: RK73K3ATE330J; VAL2: 1W; VAL1: 33(J); PA_PHASE: SCH; PA_LOCK: LOCKED; OUMERANKU: L
R26 R31 R35 R36 R41 R42 = R: SQ_PART_MODEL: RES_1; FNPARTSNAMEG: CHIP RESISTOR (2012); USEINPARTSLIST: YES; PARTNAME: GDM010000073; PARTCOMMENT: 代表セル<KC0006> がフットプリントに登録されていません。; OriginalSymbolOrigin: (5080,5080); MAXGCOUNT: 1; COMPONENTNAME: GDM010000073_package; MFSOLDERINGPROP: .; OUMEMAKER: NAE 松下電子部品; MFPACKAGEMETHOP: S; MFFORMINGDIVP: KC; MOUNTINGFORMSMD: SMD; OUMECLASSIFICATION: 表面実装用固定抵抗器; RESISTANCETOLER: F; MFMOUNTSYMBOLP: 80; POWERRATING: 125m; OUMEMAKERKATAMEI: ERJ6RQF6R8V; NUMBEROFELEMENT: 0; VAL2: 125mW; VAL1: 1(F); CDMASTERCADCELG: KC0006; PCODE: P01B000000XB; FNCLASSCODEG: P01-08; FNLEADFREETHET1GT2GMCTH1: 3_1_N; NOMINALRESISTAN: 6.8; OUMEPOWER: 1/10; OUMERESISTANCE: 8.2K; OUMECHIPSIZE: 2012; OUMECELLMEI: DR910A; PA_PHASE: SCH; PA_LOCK: LOCKED; OUMERANKU: L
R27 R32 = R: SQ_PART_MODEL: RES_1; FNPARTSNAMEG: CHIP RESISTOR (2012); USEINPARTSLIST: YES; PARTNAME: GDM010000073; PARTCOMMENT: 代表セル<KC0006> がフットプリントに登録されていません。; OriginalSymbolOrigin: (5080,5080); MAXGCOUNT: 1; COMPONENTNAME: GDM010000073_package; MFSOLDERINGPROP: .; OUMEMAKER: NAE 松下電子部品; MFPACKAGEMETHOP: S; MFFORMINGDIVP: KC; MOUNTINGFORMSMD: SMD; OUMECLASSIFICATION: 表面実装用固定抵抗器; RESISTANCETOLER: F; MFMOUNTSYMBOLP: 80; POWERRATING: 125m; OUMEMAKERKATAMEI: ERJ6RQF6R8V; NUMBEROFELEMENT: 0; VAL2: 125mW; CDMASTERCADCELG: KC0006; PCODE: P01B000000XB; FNCLASSCODEG: P01-08; FNLEADFREETHET1GT2GMCTH1: 3_1_N; NOMINALRESISTAN: 6.8; OUMEPOWER: 1/10; OUMERESISTANCE: 8.2K; OUMECHIPSIZE: 2012; OUMECELLMEI: DR910A; PA_PHASE: SCH; PA_LOCK: LOCKED; OUMERANKU: L
R39 = R: SQ_PART_MODEL: RES_22K; FNPARTSNAMEG: CHIP RESISTOR (1608); USEINPARTSLIST: YES; PARTNAME: G36010027058; OriginalSymbolOrigin: (5080,5080); MFSOLDERINGPROP: .; MFPACKAGEMETHOP: S; MFFORMINGDIVP: KC; MOUNTINGFORMSMD: SMD; FNLEADFREETHET1GT2GMCTH1: 3_1_N; OUMECLASSIFICATION: 表面実装用固定抵抗器; RESISTANCETOLER: F; ASIMVALUE: 22K; MFMOUNTSYMBOLP: 80; POWERRATING: 63m; NUMBEROFELEMENT: 0; CDMASTERCADCELG: DR802R; PCODE: P01042207426; FNCLASSCODEG: P01-08; MAXGCOUNT: 1; OUMEPOWER: 1/10; COMPONENTNAME: G36010027089_package; OUMEMAKER: KOA ＫＯＡ; OUMERESISTANCE: 8.2K; OUMECHIPSIZE: 2012; OUMECELLMEI: DR910A; OUMEMAKERKATAMEI: RK73H1JTD2202F; VAL2: 63mW; PA_PHASE: SCH; PA_LOCK: LOCKED; OUMERANKU: L
R40 = R: SQ_PART_MODEL: RES_1.5K; FNPARTSNAMEG: CHIP RESISTOR (1608); USEINPARTSLIST: YES; PARTNAME: G36010027324; OriginalSymbolOrigin: (5080,5080); MFSOLDERINGPROP: .; MFPACKAGEMETHOP: S; MFFORMINGDIVP: KC; MOUNTINGFORMSMD: SMD; FNLEADFREETHET1GT2GMCTH1: 3_1_N; OUMECLASSIFICATION: 表面実装用固定抵抗器; RESISTANCETOLER: F; ASIMVALUE: 1.5K; MFMOUNTSYMBOLP: 80; POWERRATING: 63m; NUMBEROFELEMENT: 0; CDMASTERCADCELG: DR802R; PCODE: P01042512223; FNCLASSCODEG: P01-08; MAXGCOUNT: 1; OUMEPOWER: 1/10; COMPONENTNAME: G36010027232_package; OUMEMAKER: HDK 北陸電気工業; OUMERESISTANCE: 8.2K; OUMECHIPSIZE: 2012; OUMECELLMEI: DR910A; OUMEMAKERKATAMEI: CR1/16 152FV; VAL2: 63mW; PA_PHASE: SCH; PA_LOCK: LOCKED; OUMERANKU: L
R43 = R: SQ_PART_MODEL: RES_22K; FNPARTSNAMEG: CHIP RESISTOR (1608); USEINPARTSLIST: YES; PARTNAME: G36010027089; OriginalSymbolOrigin: (5080,5080); MFSOLDERINGPROP: .; MFPACKAGEMETHOP: S; MFFORMINGDIVP: KC; MOUNTINGFORMSMD: SMD; FNLEADFREETHET1GT2GMCTH1: 3_1_N; OUMECLASSIFICATION: 表面実装用固定抵抗器; RESISTANCETOLER: F; ASIMVALUE: 22K; MFMOUNTSYMBOLP: 80; POWERRATING: 63m; NUMBEROFELEMENT: 0; CDMASTERCADCELG: DR802R; PCODE: P01042207426; FNCLASSCODEG: P01-08; MAXGCOUNT: 1; OUMEPOWER: 1/10; COMPONENTNAME: G36010027089_package; OUMEMAKER: KOA ＫＯＡ; OUMERESISTANCE: 8.2K; OUMECHIPSIZE: 2012; OUMECELLMEI: DR910A; OUMEMAKERKATAMEI: RK73H1JTD2202F; VAL2: 63mW; PA_PHASE: SCH; PA_LOCK: LOCKED; OUMERANKU: L
R46 R53 R55 R58 = R: SQ_PART_MODEL: RES_10K; FNPARTSNAMEG: CHIP RESISTOR (6432); USEINPARTSLIST: YES; PARTNAME: G36010036012; OriginalSymbolOrigin: (5080,5080); MFSOLDERINGPROP: .; MFPACKAGEMETHOP: S; MFFORMINGDIVP: KC; MOUNTINGFORMSMD: SMD; FNLEADFREETHET1GT2GMCTH1: 3_1_N; OUMECLASSIFICATION: 表面実装用固定抵抗器; RESISTANCETOLER: J; ASIMVALUE: 10K; MFMOUNTSYMBOLP: 80; POWERRATING: 1; NOMINALRESISTAN: 6.8; NUMBEROFELEMENT: 0; CDMASTERCADCELG: R8100A; PCODE: P01062003213; FNCLASSCODEG: P01-08; OUMEPOWER: 1/10; COMPONENTNAME: G36010036012_package; OUMEMAKER: KAM 釜屋電機; OUMERESISTANCE: 8.2K; OUMECHIPSIZE: 2012; OUMECELLMEI: DR910A; OUMEMAKERKATAMEI: RMC1-6R8JTE; VAL2: 1W; VAL1: 10K(F); PA_PHASE: SCH; PA_LOCK: LOCKED; OUMERANKU: L
R47-R50 R158 R159 R164-R166 = R: SQ_PART_MODEL: RES_1.5K; FNPARTSNAMEG: CHIP RESISTOR (2075); USEINPARTSLIST: YES; PARTNAME: K0100564; PARTCOMMENT: 代表セル<KCK0072> がフットプリントに登録されていません。; OriginalSymbolOrigin: (5080,5080); ASIMVALUE: 1.5K; MFSOLDERINGPROP: .; MFPACKAGEMETHOP: S; MFFORMINGDIVP: KC; MOUNTINGFORMSMD: SMD; FNLEADFREETHET1GT2GMCTH1: 3_1_N; OUMECLASSIFICATION: 表面実装用固定抵抗器; RESISTANCETOLER: F; MFMOUNTSYMBOLP: 80; POWERRATING: 2; NOMINALRESISTAN: 6m; NUMBEROFELEMENT: 0; CDMASTERCADCELG: KCK0072; FNCLASSCODEG: P01-08; MAXGCOUNT: 1; OUMEPOWER: 1/10; COMPONENTNAME: K0100564_package; OUMEMAKER: SSM 進工業; OUMERESISTANCE: 8.2K; OUMECHIPSIZE: 2012; OUMECELLMEI: DR910A; OUMEMAKERKATAMEI: RL7520(W)T-R006-F; VAL2: 3W; VAL1: 1.5K(F); PA_PHASE: SCH; PA_LOCK: LOCKED; OUMERANKU: L
R51 = R: SQ_PART_MODEL: RES_1.5K; FNPARTSNAMEG: CHIP RESISTOR (2075); USEINPARTSLIST: YES; PARTNAME: K0100564; PARTCOMMENT: 代表セル<KCK0072> がフットプリントに登録されていません。; OriginalSymbolOrigin: (5080,5080); ASIMVALUE: 1.5K; MFSOLDERINGPROP: .; MFPACKAGEMETHOP: S; MFFORMINGDIVP: KC; MOUNTINGFORMSMD: SMD; FNLEADFREETHET1GT2GMCTH1: 3_1_N; OUMECLASSIFICATION: 表面実装用固定抵抗器; RESISTANCETOLER: F; MFMOUNTSYMBOLP: 80; POWERRATING: 2; NOMINALRESISTAN: 6m; NUMBEROFELEMENT: 0; CDMASTERCADCELG: KCK0072; FNCLASSCODEG: P01-08; MAXGCOUNT: 1; OUMEPOWER: 1/10; COMPONENTNAME: K0100564_package; OUMEMAKER: SSM 進工業; OUMERESISTANCE: 8.2K; OUMECHIPSIZE: 2012; OUMECELLMEI: DR910A; OUMEMAKERKATAMEI: RL7520(W)T-R006-F; PA_PHASE: SCH; PA_LOCK: LOCKED; OUMERANKU: L
R52 = R: SQ_PART_MODEL: RES_100K; FNPARTSNAMEG: CHIP RESISTOR (6432); USEINPARTSLIST: YES; PARTNAME: G36010036012; OriginalSymbolOrigin: (5080,5080); TOLERANCE: J; ASIMVALUE: 100K; MFSOLDERINGPROP: .; MFPACKAGEMETHOP: S; MFFORMINGDIVP: KC; MOUNTINGFORMSMD: SMD; FNLEADFREETHET1GT2GMCTH1: 3_1_N; OUMECLASSIFICATION: 表面実装用固定抵抗器; MFMOUNTSYMBOLP: 80; POWERRATING: 1; NOMINALRESISTAN: 6.8; NUMBEROFELEMENT: 0; CDMASTERCADCELG: R8100A; PCODE: P01062003213; FNCLASSCODEG: P01-08; OUMEPOWER: 1/10; COMPONENTNAME: G36010036012_package; OUMEMAKER: KAM 釜屋電機; OUMERESISTANCE: 8.2K; OUMECHIPSIZE: 2012; OUMECELLMEI: DR910A; OUMEMAKERKATAMEI: RMC1-6R8JTE; PA_PHASE: SCH; PA_LOCK: LOCKED; OUMERANKU: L
R54 = R: SQ_PART_MODEL: RES_10K; FNPARTSNAMEG: CHIP RESISTOR (6432); USEINPARTSLIST: YES; PARTNAME: G36010036012; OriginalSymbolOrigin: (5080,5080); MFSOLDERINGPROP: .; MFPACKAGEMETHOP: S; MFFORMINGDIVP: KC; MOUNTINGFORMSMD: SMD; FNLEADFREETHET1GT2GMCTH1: 3_1_N; OUMECLASSIFICATION: 表面実装用固定抵抗器; RESISTANCETOLER: J; ASIMVALUE: 10K; MFMOUNTSYMBOLP: 80; POWERRATING: 1; NOMINALRESISTAN: 6.8; NUMBEROFELEMENT: 0; CDMASTERCADCELG: R8100A; PCODE: P01062003213; FNCLASSCODEG: P01-08; OUMEPOWER: 1/10; COMPONENTNAME: G36010036012_package; OUMEMAKER: KAM 釜屋電機; OUMERESISTANCE: 8.2K; OUMECHIPSIZE: 2012; OUMECELLMEI: DR910A; OUMEMAKERKATAMEI: RMC1-6R8JTE; PA_PHASE: SCH; PA_LOCK: LOCKED; OUMERANKU: L
R56 = R: SQ_PART_MODEL: RES_2.2K; FNPARTSNAMEG: CHIP RESISTOR (1608); USEINPARTSLIST: YES; PARTNAME: G36010104339; OriginalSymbolOrigin: (5080,5080); MFSOLDERINGPROP: .; MFPACKAGEMETHOP: S; MFFORMINGDIVP: KC; MOUNTINGFORMSMD: SMD; FNLEADFREETHET1GT2GMCTH1: 3_1_N; OUMECLASSIFICATION: 表面実装用固定抵抗器; RESISTANCETOLER: F; MFMOUNTSYMBOLP: 80; POWERRATING: 63m; NOMINALRESISTAN: 2.2K; NUMBEROFELEMENT: 0; CDMASTERCADCELG: DR802R; PCODE: P01042159428; FNCLASSCODEG: P01-08; MAXGCOUNT: 1; OUMEPOWER: 1/10; COMPONENTNAME: G36010104339_package; OUMEMAKER: KOA ＫＯＡ; OUMERESISTANCE: 8.2K; OUMECHIPSIZE: 2012; OUMECELLMEI: DR910A; OUMEMAKERKATAMEI: RK73H1JTD2201F; VAL2: 63mW; PA_PHASE: SCH; PA_LOCK: LOCKED; OUMERANKU: L
R57 = R: SQ_PART_MODEL: RES_1K; FNPARTSNAMEG: CHIP RESISTOR (1608); USEINPARTSLIST: YES; PARTNAME: G36010027324; OriginalSymbolOrigin: (5080,5080); MFSOLDERINGPROP: .; MFPACKAGEMETHOP: S; MFFORMINGDIVP: KC; MOUNTINGFORMSMD: SMD; FNLEADFREETHET1GT2GMCTH1: 3_1_N; OUMECLASSIFICATION: 表面実装用固定抵抗器; RESISTANCETOLER: F; ASIMVALUE: 1K; MFMOUNTSYMBOLP: 80; POWERRATING: 63m; NUMBEROFELEMENT: 0; CDMASTERCADCELG: DR802R; PCODE: P01042521225; FNCLASSCODEG: P01-08; MAXGCOUNT: 1; OUMEPOWER: 1/10; COMPONENTNAME: G36010027324_package; OUMEMAKER: HDK 北陸電気工業; OUMERESISTANCE: 8.2K; OUMECHIPSIZE: 2012; OUMECELLMEI: DR910A; OUMEMAKERKATAMEI: CR1/16 102FV; VAL2: 63mW; PA_PHASE: SCH; PA_LOCK: LOCKED; OUMERANKU: L
R59 = R: SQ_PART_MODEL: RES_10K; FNPARTSNAMEG: CHIP RESISTOR (1608); USEINPARTSLIST: YES; PARTNAME: G36010027249; OriginalSymbolOrigin: (5080,5080); MFSOLDERINGPROP: .; MFPACKAGEMETHOP: S; MFFORMINGDIVP: KC; MOUNTINGFORMSMD: SMD; FNLEADFREETHET1GT2GMCTH1: 3_1_N; OUMECLASSIFICATION: 表面実装用固定抵抗器; RESISTANCETOLER: F; ASIMVALUE: 10K; MFMOUNTSYMBOLP: 80; POWERRATING: 63m; NUMBEROFELEMENT: 0; CDMASTERCADCELG: DR802R; PCODE: P01042049A26; FNCLASSCODEG: P01-08; MAXGCOUNT: 1; OUMEPOWER: 1/10; COMPONENTNAME: G36010027034_package; OUMEMAKER: SAM 三星電機; OUMERESISTANCE: 8.2K; OUMECHIPSIZE: 2012; OUMECELLMEI: DR910A; OUMEMAKERKATAMEI: RC1608F103CS; VAL2: 63mW; PA_PHASE: SCH; PA_LOCK: LOCKED; OUMERANKU: L
R160 R161 = R: SQ_PART_MODEL: RES_100K; FNPARTSNAMEG: CHIP RESISTOR (6432); USEINPARTSLIST: YES; PARTNAME: G36010036012; OriginalSymbolOrigin: (5080,5080); TOLERANCE: J; ASIMVALUE: 100K; MFSOLDERINGPROP: .; MFPACKAGEMETHOP: S; MFFORMINGDIVP: KC; MOUNTINGFORMSMD: SMD; FNLEADFREETHET1GT2GMCTH1: 3_1_N; OUMECLASSIFICATION: 表面実装用固定抵抗器; MFMOUNTSYMBOLP: 80; POWERRATING: 1; NOMINALRESISTAN: 6.8; NUMBEROFELEMENT: 0; CDMASTERCADCELG: R8100A; PCODE: P01062003213; FNCLASSCODEG: P01-08; OUMEPOWER: 1/10; COMPONENTNAME: G36010036012_package; OUMEMAKER: KAM 釜屋電機; OUMERESISTANCE: 8.2K; OUMECHIPSIZE: 2012; OUMECELLMEI: DR910A; OUMEMAKERKATAMEI: RMC1-6R8JTE; VAL2: 1W; VAL1: 100K(F); PA_PHASE: SCH; PA_LOCK: LOCKED; OUMERANKU: L
T1 = T-16P: USEINPARTSLIST: YES; PARTNAME: ETD39; SAVEAREA0: -36922,-744,61114,73099; SAVECOUNT: 21; TIME: 15:53:21; UPDATEUSER: CR5000; UPDATETIME: 16:11:03; OriginalSymbolOrigin: (5080,68580); VAL3: 750344423; MAXGCOUNT: 1; COMPONENTNAME: pinass:T-16P_func:T-16P; OUMEMAKER: WURTH
T2 = T2CT: USEINPARTSLIST: YES; TIME: 18:03:00; UPDATEUSER: q91866sr; SAVECOUNT: 2; SAVEAREA0: -11493,-43,34436,25356; OriginalSymbolOrigin: (5080,22860); MAXGCOUNT: 1; COMPONENTNAME: pinass:T2CT_func:T2CT; OUMEMAKER: WURTH
TP1-TP24 = TP: USEINPARTSLIST: YES; PARTNAME: ZS_DE050A; OUMEPARTTYPE: PJ; OriginalSymbolOrigin: (0,7620); VAL3: HYT-4024BR; MAXGCOUNT: 1; COMPONENTNAME: ZS_DE050A_package; QUADMODEL: dummymodel
U?#1 = WAKU_DEF100: PLOTTIME: HH:MM; SAVEAREA0: 218350,-40131,416688,63935; TIME: 14:30:25; UPDATEUSER: t5459927; UPDATETIME: 13:20:45; SAVECOUNT: 5; OriginalSymbolOrigin: (10160,284480)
